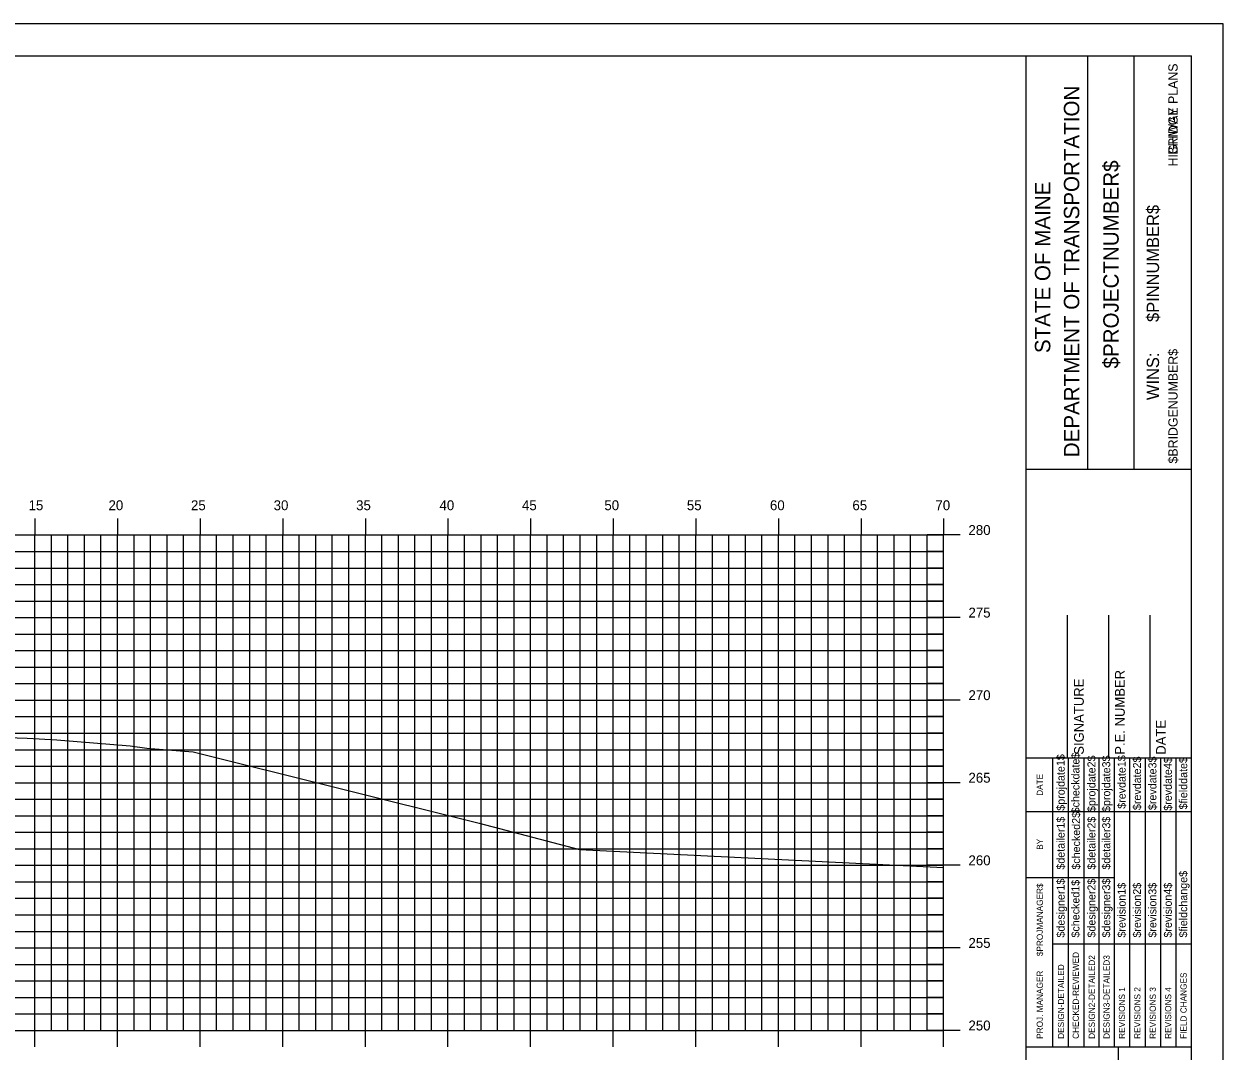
# Model space of a CAD drawing. Extents: x 1168600 to 1177589, y 610178 to 611246.
# Drawn here: x 1176308.5 to 1176381.1, y 610948.3 to 611010.5 of the extents above; entities that cross this region are included whole.
import ezdxf

# ---------------------------------------------------------------- set-up
doc = ezdxf.new("R2010")
doc.units = 0
for name, color, linetype in [('_Construction', 7, 'Continuous'), ('_Station Equation', 7, 'Continuous'), ('BORDER', 7, 'Continuous'), ('H_V ANNOTATION', 7, 'Continuous'), ('MAJOR', 7, 'Continuous'), ('MINOR', 7, 'Continuous')]:
    doc.layers.add(name, color=color, linetype=linetype)

msp = doc.modelspace()

# ---------------------------------------------------------------- linework, layer by layer
at = {"layer": '_Construction'}
for p, q in [((1176379.176, 611008.596), (1176219.176, 611008.596)), ((1176369.176, 610903.599), (1176369.176, 611008.599)), ((1176372.905, 610983.593), (1176372.905, 611008.593)), ((1176375.7, 610983.593), (1176375.7, 611008.593)), ((1176379.176, 610903.599), (1176379.176, 611008.599)), ((1176369.177, 610983.59), (1176379.176, 610983.59)), ((1176371.676, 610966.099), (1176371.676, 610974.747)), ((1176374.176, 610966.099), (1176374.176, 610974.747)), ((1176376.676, 610966.099), (1176376.676, 610974.747)), ((1176369.176, 610966.099), (1176379.176, 610966.099)), ((1176369.176, 610948.599), (1176379.176, 610948.599)), ((1176374.767, 610913.599), (1176374.767, 610948.599))]:
    msp.add_line(p, q, dxfattribs=at)
msp.add_lwpolyline([(1176211.083, 610900.537), (1176381.083, 610900.537), (1176381.083, 611010.537), (1176211.083, 611010.537)], close=True, dxfattribs=at)
for points in [[(1176370.791, 610962.849), (1176370.791, 610966.099)], [(1176371.724, 610948.602), (1176371.724, 610966.099)], [(1176372.655, 610966.099), (1176372.655, 610948.602)], [(1176373.587, 610948.602), (1176373.587, 610966.099)], [(1176374.519, 610948.602), (1176374.519, 610966.099)], [(1176375.45, 610948.602), (1176375.45, 610966.099)], [(1176376.382, 610948.602), (1176376.382, 610966.099)], [(1176377.314, 610948.602), (1176377.314, 610966.099)], [(1176378.245, 610948.602), (1176378.245, 610966.099)], [(1176370.792, 610948.602), (1176370.792, 610965.393)], [(1176369.176, 610962.849), (1176379.176, 610962.849)], [(1176369.176, 610958.849), (1176370.792, 610958.849)], [(1176370.791, 610958.849), (1176374.518, 610958.849)], [(1176370.791, 610954.849), (1176379.176, 610954.849)]]:
    msp.add_lwpolyline(points, dxfattribs=at)
at = {"layer": '_Station Equation'}
for points in [[(1176306.888, 610967.353), (1176308.703, 610967.295), (1176310.502, 610967.193), (1176314.945, 610966.833), (1176315.958, 610966.681), (1176316.931, 610966.607), (1176318.758, 610966.469), (1176336.062, 610962.151), (1176342.143, 610960.556), (1176364.176, 610959.464)], [(1176306.889, 610967.353), (1176308.703, 610967.295), (1176310.501, 610967.193), (1176314.945, 610966.833), (1176315.958, 610966.681), (1176316.931, 610966.607), (1176318.758, 610966.469), (1176336.062, 610962.151), (1176342.143, 610960.556), (1176364.176, 610959.464)]]:
    msp.add_lwpolyline(points, dxfattribs=at)
at = {"layer": 'MAJOR'}
for p, q in [((1176309.176, 610980.598), (1176309.176, 610979.596)), ((1176314.176, 610980.598), (1176314.176, 610979.596)), ((1176319.176, 610980.598), (1176319.176, 610979.596)), ((1176324.176, 610980.598), (1176324.176, 610979.596)), ((1176329.176, 610980.598), (1176329.176, 610979.596)), ((1176334.176, 610980.598), (1176334.176, 610979.596)), ((1176339.176, 610980.598), (1176339.176, 610979.596)), ((1176344.176, 610980.598), (1176344.176, 610979.596)), ((1176349.176, 610980.598), (1176349.176, 610979.596)), ((1176354.176, 610980.598), (1176354.176, 610979.596)), ((1176359.176, 610980.598), (1176359.176, 610979.596)), ((1176364.176, 610980.598), (1176364.176, 610979.596)), ((1176224.176, 610979.596), (1176364.176, 610979.596)), ((1176224.176, 610979.596), (1176364.176, 610979.596)), ((1176309.176, 610949.596), (1176309.176, 610979.596)), ((1176314.176, 610949.596), (1176314.176, 610979.596)), ((1176319.176, 610949.596), (1176319.176, 610979.596)), ((1176324.176, 610949.596), (1176324.176, 610979.596)), ((1176329.176, 610949.596), (1176329.176, 610979.596)), ((1176334.176, 610949.596), (1176334.176, 610979.596)), ((1176339.176, 610949.596), (1176339.176, 610979.596)), ((1176344.176, 610949.596), (1176344.176, 610979.596)), ((1176349.176, 610949.596), (1176349.176, 610979.596)), ((1176354.176, 610949.596), (1176354.176, 610979.596)), ((1176359.176, 610949.596), (1176359.176, 610979.596)), ((1176365.178, 610979.596), (1176363.174, 610979.596)), ((1176364.176, 610949.596), (1176364.176, 610979.596)), ((1176364.176, 610949.596), (1176364.176, 610979.596)), ((1176224.176, 610974.596), (1176364.176, 610974.596)), ((1176365.178, 610974.596), (1176363.174, 610974.596)), ((1176224.176, 610969.596), (1176364.176, 610969.596)), ((1176365.178, 610969.596), (1176363.174, 610969.596)), ((1176224.176, 610964.596), (1176364.176, 610964.596)), ((1176365.178, 610964.596), (1176363.174, 610964.596)), ((1176224.176, 610959.596), (1176364.176, 610959.596)), ((1176365.178, 610959.596), (1176363.174, 610959.596)), ((1176224.176, 610954.596), (1176364.176, 610954.596)), ((1176365.178, 610954.596), (1176363.174, 610954.596)), ((1176224.176, 610949.596), (1176364.176, 610949.596)), ((1176224.176, 610949.596), (1176364.176, 610949.596)), ((1176309.176, 610948.594), (1176309.176, 610949.596)), ((1176314.176, 610948.594), (1176314.176, 610949.596)), ((1176319.176, 610948.594), (1176319.176, 610949.596)), ((1176324.176, 610948.594), (1176324.176, 610949.596)), ((1176329.176, 610948.594), (1176329.176, 610949.596)), ((1176334.176, 610948.594), (1176334.176, 610949.596)), ((1176339.176, 610948.594), (1176339.176, 610949.596)), ((1176344.176, 610948.594), (1176344.176, 610949.596)), ((1176349.176, 610948.594), (1176349.176, 610949.596)), ((1176354.176, 610948.594), (1176354.176, 610949.596)), ((1176359.176, 610948.594), (1176359.176, 610949.596)), ((1176365.178, 610949.596), (1176363.174, 610949.596)), ((1176364.176, 610948.594), (1176364.176, 610949.596))]:
    msp.add_line(p, q, dxfattribs=at)
at = {"layer": 'MINOR'}
for p, q in [((1176310.176, 610949.596), (1176310.176, 610979.596)), ((1176311.176, 610949.596), (1176311.176, 610979.596)), ((1176312.176, 610949.596), (1176312.176, 610979.596)), ((1176313.176, 610949.596), (1176313.176, 610979.596)), ((1176315.176, 610949.596), (1176315.176, 610979.596)), ((1176316.176, 610949.596), (1176316.176, 610979.596)), ((1176317.176, 610949.596), (1176317.176, 610979.596)), ((1176318.176, 610949.596), (1176318.176, 610979.596)), ((1176320.176, 610949.596), (1176320.176, 610979.596)), ((1176321.176, 610949.596), (1176321.176, 610979.596)), ((1176322.176, 610949.596), (1176322.176, 610979.596)), ((1176323.176, 610949.596), (1176323.176, 610979.596)), ((1176325.176, 610949.596), (1176325.176, 610979.596)), ((1176326.176, 610949.596), (1176326.176, 610979.596)), ((1176327.176, 610949.596), (1176327.176, 610979.596)), ((1176328.176, 610949.596), (1176328.176, 610979.596)), ((1176330.176, 610949.596), (1176330.176, 610979.596)), ((1176331.176, 610949.596), (1176331.176, 610979.596)), ((1176332.176, 610949.596), (1176332.176, 610979.596)), ((1176333.176, 610949.596), (1176333.176, 610979.596)), ((1176335.176, 610949.596), (1176335.176, 610979.596)), ((1176336.176, 610949.596), (1176336.176, 610979.596)), ((1176337.176, 610949.596), (1176337.176, 610979.596)), ((1176338.176, 610949.596), (1176338.176, 610979.596)), ((1176340.176, 610949.596), (1176340.176, 610979.596)), ((1176341.176, 610949.596), (1176341.176, 610979.596)), ((1176342.176, 610949.596), (1176342.176, 610979.596)), ((1176343.176, 610949.596), (1176343.176, 610979.596)), ((1176345.176, 610949.596), (1176345.176, 610979.596)), ((1176346.176, 610949.596), (1176346.176, 610979.596)), ((1176347.176, 610949.596), (1176347.176, 610979.596)), ((1176348.176, 610949.596), (1176348.176, 610979.596)), ((1176350.176, 610949.596), (1176350.176, 610979.596)), ((1176351.176, 610949.596), (1176351.176, 610979.596)), ((1176352.176, 610949.596), (1176352.176, 610979.596)), ((1176353.176, 610949.596), (1176353.176, 610979.596)), ((1176355.176, 610949.596), (1176355.176, 610979.596)), ((1176356.176, 610949.596), (1176356.176, 610979.596)), ((1176357.176, 610949.596), (1176357.176, 610979.596)), ((1176358.176, 610949.596), (1176358.176, 610979.596)), ((1176360.176, 610949.596), (1176360.176, 610979.596)), ((1176361.176, 610949.596), (1176361.176, 610979.596)), ((1176362.176, 610949.596), (1176362.176, 610979.596)), ((1176363.176, 610949.596), (1176363.176, 610979.596)), ((1176224.176, 610978.596), (1176364.176, 610978.596)), ((1176364.176, 610978.596), (1176363.174, 610978.596)), ((1176224.176, 610977.596), (1176364.176, 610977.596)), ((1176364.176, 610977.596), (1176363.174, 610977.596)), ((1176224.176, 610976.596), (1176364.176, 610976.596)), ((1176364.176, 610976.596), (1176363.174, 610976.596)), ((1176224.176, 610975.596), (1176364.176, 610975.596)), ((1176364.176, 610975.596), (1176363.174, 610975.596)), ((1176224.176, 610973.596), (1176364.176, 610973.596)), ((1176364.176, 610973.596), (1176363.174, 610973.596)), ((1176224.176, 610972.596), (1176364.176, 610972.596)), ((1176364.176, 610972.596), (1176363.174, 610972.596)), ((1176224.176, 610971.596), (1176364.176, 610971.596)), ((1176364.176, 610971.596), (1176363.174, 610971.596)), ((1176224.176, 610970.596), (1176364.176, 610970.596)), ((1176364.176, 610970.596), (1176363.174, 610970.596)), ((1176224.176, 610968.596), (1176364.176, 610968.596)), ((1176364.176, 610968.596), (1176363.174, 610968.596)), ((1176224.176, 610967.596), (1176364.176, 610967.596)), ((1176364.176, 610967.596), (1176363.174, 610967.596)), ((1176224.176, 610966.596), (1176364.176, 610966.596)), ((1176364.176, 610966.596), (1176363.174, 610966.596)), ((1176224.176, 610965.596), (1176364.176, 610965.596)), ((1176364.176, 610965.596), (1176363.174, 610965.596)), ((1176224.176, 610963.596), (1176364.176, 610963.596)), ((1176364.176, 610963.596), (1176363.174, 610963.596)), ((1176224.176, 610962.596), (1176364.176, 610962.596)), ((1176364.176, 610962.596), (1176363.174, 610962.596)), ((1176224.176, 610961.596), (1176364.176, 610961.596)), ((1176364.176, 610961.596), (1176363.174, 610961.596)), ((1176224.176, 610960.596), (1176364.176, 610960.596)), ((1176364.176, 610960.596), (1176363.174, 610960.596)), ((1176224.176, 610958.596), (1176364.176, 610958.596)), ((1176364.176, 610958.596), (1176363.174, 610958.596)), ((1176224.176, 610957.596), (1176364.176, 610957.596)), ((1176364.176, 610957.596), (1176363.174, 610957.596)), ((1176224.176, 610956.596), (1176364.176, 610956.596)), ((1176364.176, 610956.596), (1176363.174, 610956.596)), ((1176224.176, 610955.596), (1176364.176, 610955.596)), ((1176364.176, 610955.596), (1176363.174, 610955.596)), ((1176224.176, 610953.596), (1176364.176, 610953.596)), ((1176364.176, 610953.596), (1176363.174, 610953.596)), ((1176224.176, 610952.596), (1176364.176, 610952.596)), ((1176364.176, 610952.596), (1176363.174, 610952.596)), ((1176224.176, 610951.596), (1176364.176, 610951.596)), ((1176364.176, 610951.596), (1176363.174, 610951.596)), ((1176224.176, 610950.596), (1176364.176, 610950.596)), ((1176364.176, 610950.596), (1176363.174, 610950.596))]:
    msp.add_line(p, q, dxfattribs=at)

# ---------------------------------------------------------------- texts
at = {"layer": '_Construction'}
for s, height, p in [('BRIDGE PLANS', 0.55901, (1176378.334, 611002.62)), ('HIGHWAY PLANS', 0.55901, (1176378.334, 611001.911)), ('DEPARTMENT OF TRANSPORTATION', 0.93176, (1176372.383, 610984.302)), ('$PROJECTNUMBER$', 0.93176, (1176374.768, 610989.675)), ('STATE OF MAINE', 0.93176, (1176370.631, 610990.608)), ('$PINNUMBER$', 0.74527, (1176377.213, 610992.493)), ('$BRIDGENUMBER$', 0.55901, (1176378.334, 610983.926)), ('SIGNATURE', 0.5906, (1176372.657, 610966.291)), ('P.E. NUMBER', 0.59055, (1176375.137, 610966.291)), ('DATE', 0.5906, (1176377.617, 610966.291)), ('$projdate1$', 0.48455, (1176371.499, 610962.899)), ('$checkdate$', 0.48455, (1176372.394, 610962.742)), ('$projdate2$', 0.48455, (1176373.363, 610962.821)), ('$projdate3$', 0.48455, (1176374.257, 610962.821)), ('$revdate1$', 0.4845, (1176375.189, 610963.017)), ('$revdate2$', 0.4845, (1176376.12, 610962.939)), ('$revdate3$', 0.4845, (1176377.052, 610962.939)), ('$revdate4$', 0.4845, (1176377.984, 610962.899)), ('$fielddate$', 0.48455, (1176378.915, 610962.978)), ('DATE', 0.3714, (1176370.18, 610963.805)), ('$checked2$', 0.4845, (1176372.431, 610959.334)), ('$detailer1$', 0.48455, (1176371.499, 610959.334)), ('$detailer2$', 0.48455, (1176373.363, 610959.334)), ('$detailer3$', 0.48455, (1176374.257, 610959.334)), ('BY', 0.3714, (1176370.18, 610960.534)), ('$fieldchange$', 0.48455, (1176378.915, 610955.222)), ('$PROJMANAGER$', 0.37275, (1176370.18, 610954.094)), ('$designer1$', 0.48455, (1176371.499, 610955.222)), ('$checked1$', 0.4845, (1176372.394, 610955.222)), ('$designer2$', 0.48455, (1176373.363, 610955.222)), ('$designer3$', 0.48455, (1176374.257, 610955.222)), ('$revision1$', 0.48455, (1176375.189, 610955.222)), ('$revision2$', 0.48455, (1176376.12, 610955.222)), ('$revision3$', 0.48455, (1176377.052, 610955.222)), ('$revision4$', 0.48455, (1176377.984, 610955.222)), ('CHECKED-REVIEWED', 0.37275, (1176372.357, 610949.087)), ('DESIGN2-DETAILED2', 0.37275, (1176373.326, 610949.087)), ('DESIGN3-DETAILED3', 0.37275, (1176374.221, 610949.087)), ('DESIGN-DETAILED', 0.37275, (1176371.463, 610949.087)), ('PROJ. MANAGER', 0.37275, (1176370.18, 610949.087)), ('FIELD CHANGES', 0.37275, (1176378.879, 610949.087)), ('REVISIONS 1', 0.37275, (1176375.152, 610949.087)), ('REVISIONS 2', 0.37275, (1176376.084, 610949.087)), ('REVISIONS 3', 0.37275, (1176377.016, 610949.087)), ('REVISIONS 4', 0.37275, (1176377.947, 610949.087))]:
    msp.add_text(s, height=height, rotation=90, dxfattribs=at).set_placement(p)
at = {"layer": 'BORDER'}
msp.add_text('WINS:', height=0.7453, rotation=90, dxfattribs=at).set_placement((1176377.211, 610987.764))
at = {"layer": 'H_V ANNOTATION'}
for s, p in [('15', (1176308.793, 610981.096)), ('20', (1176313.63, 610981.096)), ('25', (1176318.622, 610981.096)), ('30', (1176323.625, 610981.096)), ('35', (1176328.617, 610981.096)), ('40', (1176333.662, 610981.096)), ('45', (1176338.654, 610981.096)), ('50', (1176343.641, 610981.096)), ('55', (1176348.633, 610981.096)), ('60', (1176353.662, 610981.096)), ('65', (1176358.654, 610981.096)), ('70', (1176363.678, 610981.096)), ('280', (1176365.676, 610979.596)), ('275', (1176365.676, 610974.596)), ('270', (1176365.676, 610969.596)), ('265', (1176365.676, 610964.596)), ('260', (1176365.676, 610959.596)), ('255', (1176365.676, 610954.596)), ('250', (1176365.676, 610949.596))]:
    msp.add_text(s, height=0.6, dxfattribs=at).set_placement(p)

doc.saveas('drawing.dxf')
